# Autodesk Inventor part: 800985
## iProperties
Created: 2007-03
Part Number: 800985
Material: Steel, High Strength Low Alloy
Description: RETAINING RING 12 X 1
Document SubType Name: Modeling
Standard: JIS B 2804
Designer: JJ
Standards Organization: JIS
Language: en-US
Size Designation: 12x1
Categories: <MemberInstance><Categories><Category DisplayName="Shaft Parts" InternalName="7f7aeb1f-a693-4053-b835-cee3144e0d98" Mnemonic="SHFT"><Category DisplayName="Circl
Density: 7.84 g/cm^3
Mass: 0.565729 g
Surface Area: 2.44204 cm^2
Volume: 0.0721593 cm^3
Component Category: Fasteners
IsCustomPart: 0
Author: JJ
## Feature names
1. Body [Extrusion]
